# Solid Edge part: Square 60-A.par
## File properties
Title: Square 60 x 51 Cm da incasso
Author: DESYS
Template: Normal.par
Last saved by: PIM_1
Revision: 10
Application: Solid Edge
Tipo di contenuto documento: 0
Precisione: 0,990
Document Number: 8007/A
Revision: 0
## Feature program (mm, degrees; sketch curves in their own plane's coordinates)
sketch for "unnamed Protrusion 1" plane through (0, 0, 0) normal (0, 0, 1) x-axis (1, 0, 0)
  line (-300, -255) -> (300, -255)
  line (300, -255) -> (300, 255)
  line (300, 255) -> (-300, 255)
  line (-300, 255) -> (-300, -255)
extrude "unnamed Protrusion 1" add finite 160 along -normal
sketch for "ExtrudedCutout_1" plane through (0, -210, -80) normal (0, -1, 0) x-axis (1, 0, 0)
  arc centre (0, 283.125) radius 303.125 from (-225, 80) to (225, 80) ccw
extrude "ExtrudedCutout_1" cut finite 330 along -normal  Profile_Plane1_Distance = 45 mm
sketch for "ExtrudedCutout_2" plane through (0, 0, -160) normal (0, 0, -1) x-axis (1, 0, 0)
  line (285, -145) -> (285, 235)
  line (-285, 235) -> (285, 235)
  line (-285, 235) -> (-285, -145)
  line (-285, -145) -> (285, -145)
extrude "ExtrudedCutout_2" cut finite 75 along -normal
sketch for "ExtrudedCutout_3" plane through (0, -55, -160) normal (0, 0, -1) x-axis (1, 0, 0)
  line (-190, -285) -> (190, -285)
  line (190, -285) -> (190, -180)
  line (190, -180) -> (-190, -180)
  line (-190, -180) -> (-190, -285)
extrude "ExtrudedCutout_3" cut finite 145 along -normal
sketch for "ExtrudedCutout_4" plane through (0, 125, -87.5) normal (0, 1, 0) x-axis (1, 0, 0)
  line (-200, 68.5) -> (-188.2769, 10.0335)
  arc centre (-182.394, 11.2131) radius 6 from (-188.2769, 10.0335) to (-180.6128, 5.4836) ccw
  arc centre (-2.5, -567.47) radius 600 from (-180.6128, 5.4836) to (175.6128, 5.4836) cw
  arc centre (177.394, 11.2131) radius 6 from (175.6128, 5.4836) to (183.2769, 10.0335) ccw
  line (195, 68.5) -> (183.2769, 10.0335)
extrude "ExtrudedCutout_4" cut finite 265 along -normal
sketch for "unnamed Protrusion 2" plane through (0, -55, -160) normal (0, 0, -1) x-axis (0, -1, 0)
  circle centre (-15, 0) radius 35
extrude "unnamed Protrusion 2" add through along -normal
sketch for "Foro_1" plane through (0, 10, -160) normal (0, 0, -1) x-axis (0, -1, 0)
  hole centre (50, 0) bore radius 22.5
hole "Foro_1" diameter 45 through
draft "Draft_1"  Angles1 = 10 deg
sketch for "Foro_2" plane through (0, 0, 0) normal (0, 0, 1) x-axis (0, -1, 0)
  hole centre (-185, 0) bore radius 17.5
hole "Foro_2" diameter 35 through
sketch for "unnamed Protrusion 3" plane through (0, 0, 0) normal (1, 0, 0) x-axis (0, 1, 0)
  line (-5, -151.616) -> (124.756, -145.4672)
  arc centre (123.8093, -125.4896) radius 20 from (124.756, -145.4672) to (143.4613, -129.2045) ccw
  line (143.4613, -129.2045) -> (164.9779, -15.3818)
extrude "unnamed Protrusion 3" add to key point symmetric
fillet "Rotondo_1" radius 5
fillet "Rotondo_2" radius 10
fillet "Rotondo_3" radius 2
fillet "Rotondo_7" radius 5
fillet "Rotondo_9" radius 5
fillet "Rotondo_10" radius 10
sketch for "Foro_3" plane through (0, 0, 0) normal (0, -1, 0) x-axis (1, 0, 0)
  hole centre (0, -25) bore radius 10
hole "Foro_3" diameter 20 finite
fillet "Rotondo_11" radius 5  Radii2 = 10 mm
fillet "Rotondo_12" radius 5
fillet "Rotondo_13" radius 10
fillet "Rotondo_14" radius 5
fillet "Rotondo_15" radius 5
fillet "Rotondo_16" radius 10
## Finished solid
Body 1: solid body, 152 faces, 336 edges, 186 vertices.
  Faces by surface: cylinder 72, plane 32, blend 25, sphere 17, torus 6
  Edges by curve: line 141, circle 112, ellipse 46, intersection 37
Bounding box of the edges (mm; curved faces can reach further): 600.000 x 510.000 x 160.000, from (-300, -255, -160) to (300, 255, 0).
Cylindrical faces by radius (mm): R5 x56, R6 x2, R10 x8, R17.5 x1, R20 x1, R22.5 x1, R35 x1, R303.125 x1, R600 x1
Toroidal faces (ring radius, tube radius in mm): R10 r5 x2, R15 r5 x2, R19.5 r2 x1, R30 r5 x1
Spherical faces by radius (mm): R5 x17
Planar faces by outward normal: +x 3, +y 3, +z 1, -x 3, -y 4, -z 5, oblique 13
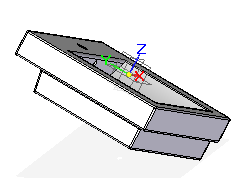
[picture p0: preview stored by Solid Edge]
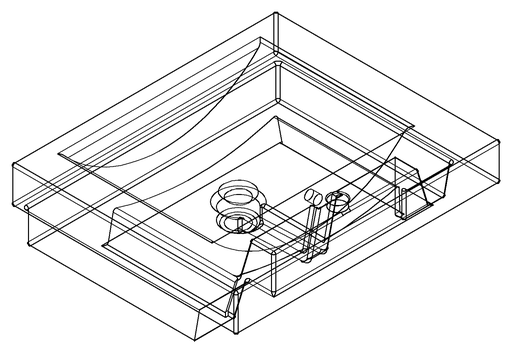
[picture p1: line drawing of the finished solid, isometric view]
